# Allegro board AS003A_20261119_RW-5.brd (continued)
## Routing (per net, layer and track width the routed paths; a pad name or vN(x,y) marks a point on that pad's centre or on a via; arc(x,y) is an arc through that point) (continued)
D11813: length 195.8
  L09_DIG w0.081: D118.13 189.31,77.39 189.31,101.16 218.35,130.2 255.78,130.2 272.55,146.97 272.55,151.71 285.02,164.19 285.02,166.46 293.11,174.55 293.11,176.52 294.92,178.34 294.92,190.15 293.55,191.52 293.55,197.45 292.91,198.09 292.91,199.91 292.43,200.39 292.43,201.55
  L09_DIG w0.102: v1(292.83,204.63) 292.43,204.23 292.43,201.55
D11814: length 314.6
  L05_DIG w0.079: D118.14 194.68,80.38 194.68,81.41 196.02,82.75 202.22,82.75 205.57,79.39 205.57,30.02 210.6,24.99 225.11,24.99 226.83,26.71 226.83,126.96 237.73,137.87 237.73,148.71 246.7,157.67 246.7,197.45 252.08,202.84 252.08,208.84 254.24,210.99 260.49,210.99 263.71,214.2 275.91,214.2 276.93,215.22 277.52,215.22 277.73,215.43 277.75,215.43
  L05_DIG w0.102: 277.75,215.43 281.23,215.43 v1(281.63,215.03)
D11815: length 196
  L09_DIG w0.081: 293.23,201.55 293.23,199 294.08,198.15 294.85,198.15 295.38,197.62 295.38,192.76 297.87,190.27 297.87,177.64 286.78,166.56 286.78,162.78 276.08,152.08 276.08,148.13 256.31,128.36 219.19,128.36 194.44,103.61 194.44,77.34 D118.15
  L09_DIG w0.102: 293.23,201.55 293.23,204.23 v1(293.63,204.63)
D11816: length 314.6
  L05_DIG w0.079: D118.16 196.93,79.93 195.48,79.93 195.06,80.35 195.06,81.25 196.18,82.37 202.06,82.37 205.19,79.23 205.19,29.86 210.44,24.61 225.27,24.61 227.21,26.55 227.21,126.8 238.12,137.71 238.12,148.55 247.08,157.51 247.08,197.29 252.47,202.68 252.47,208.68 254.4,210.6 260.65,210.6 263.87,213.82 276.07,213.82 277.09,214.84 277.52,214.84 277.73,214.63 277.75,214.63
  L05_DIG w0.102: v1(280.83,215.03) 280.43,214.63 277.75,214.63
D11901: length 229.7
  L32_DIG w0.081: D119.01 161.29,57.15 161.29,134.87 219.52,193.1 236.15,193.1 246.19,203.13 274.97,203.13 275.69,203.85 275.69,206.66 277.26,208.23 277.75,208.23
  L32_DIG w0.102: 277.75,208.23 278.83,208.23 v1(279.23,207.83)
D11902: length 272.4
  L30_DIG w0.081: 277.75,212.23 276.07,212.23 275.79,211.95 268.6,211.95 264.71,215.84 252.36,215.84 251.76,216.44 224.77,216.44 224.45,216.11 183.11,216.11 154.1,187.1 154.1,123.82 161.14,116.78 161.14,59.84 D119.02
  L30_DIG w0.102: 277.75,212.23 279.63,212.23 v1(280.03,211.83)
D11903: length 273.7
  L32_DIG w0.081: 277.75,206.63 277.24,206.63 276.45,205.84 276.45,202.69 275.43,201.66 249.59,201.66 238.72,190.79 219.99,190.79 216.8,187.6 216.8,149.01 208.67,140.88 173.49,140.88 173.28,141.09 173.28,141.38 173.49,141.59 183.51,141.59 183.72,141.8 183.72,142.09 183.5,142.31 171.51,142.31 166.29,137.09 166.29,57.07 D119.03
  L32_DIG w0.102: v1(282.43,206.23) 282.03,206.63 277.75,206.63
D11904: length 249.7
  L30_DIG w0.081: 277.75,211.43 276.9,211.43 276.13,210.66 268.7,210.66 265.48,213.88 251.68,213.88 250.25,215.32 226.61,215.32 225.03,213.73 206.96,213.73 185.95,192.73 185.95,168.74 184.38,167.16 184.38,159.16 185.51,158.03 185.51,128.64 166.46,109.59 166.46,59.6 D119.04
  L30_DIG w0.102: 277.75,211.43 279.63,211.43 v1(280.03,211.03)
D11905: length 237.1
  L32_DIG w0.081: D119.05 171.47,57.17 171.47,121.74 179.63,129.91 245.93,129.91 263.79,147.77 263.79,194.61 269.21,200.03 278.72,200.03 279.63,200.94 279.63,201.55
  L32_DIG w0.102: 279.63,201.55 279.63,202.63 v1(280.03,203.03)
D11906: length 242.9
  L30_DIG w0.081: 277.75,210.63 276.89,210.63 276.51,210.25 267.98,210.25 265.56,212.68 225.02,212.68 223.94,211.6 207.32,211.6 187.67,191.95 187.67,123.03 171.58,106.94 171.58,59.56 D119.06
  L30_DIG w0.102: 277.75,210.63 279.63,210.63 v1(280.03,210.23)
D11907: length 229
  L32_DIG w0.081: 282.03,201.55 282.03,200.81 280.88,199.66 280.88,197.2 280.15,196.47 277.08,196.47 275.17,194.56 275.17,190.81 271.49,187.13 271.49,161.36 265.73,155.6 265.73,147.42 245.89,127.58 184.98,127.58 176.59,119.19 176.59,57.21 D119.07
  L32_DIG w0.102: 282.03,201.55 282.03,202.63 v1(282.43,203.03)
D11908: length 239.4
  L30_DIG w0.081: D119.08 176.58,59.64 176.58,105.77 188.59,117.77 188.59,190.9 205.49,207.81 219.31,207.81 220.99,209.5 223.81,209.5 226.11,211.8 264.86,211.8 267.63,209.03 277.75,209.03
  L30_DIG w0.102: v1(280.03,208.63) 279.63,209.03 277.75,209.03
D11909: length 225.6
  L32_DIG w0.081: 283.63,201.55 283.63,200.58 282.52,199.47 282.52,197.2 280.13,194.82 279.57,194.82 278.92,194.17 278.92,193.62 277.56,192.26 276.23,192.26 275.61,191.65 275.61,189.58 273.86,187.83 273.86,173.09 272.48,171.71 272.48,157.63 268,153.15 268,147.52 244.58,124.1 185.88,124.1 181.65,119.87 181.65,57.19 D119.09
  L32_DIG w0.102: v1(284.03,203.03) 283.63,202.63 283.63,201.55
D11910: length 235.7
  L30_DIG w0.081: 277.75,208.23 276.05,208.23 275.75,208.53 266.96,208.53 264.7,210.79 253.65,210.79 247.74,204.88 204.05,204.88 190.8,191.63 190.8,139.75 189.74,138.7 189.74,111.63 181.84,103.72 181.84,59.46 D119.10
  L30_DIG w0.102: v1(280.03,207.83) 279.63,208.23 277.75,208.23
D11911: length 276.9
  L32_DIG w0.081: D119.11 186.61,57.07 186.61,113.15 190.58,117.12 218.18,117.12 218.39,116.91 218.39,116.62 218.18,116.41 192.9,116.41 192.7,116.2 192.7,115.91 192.92,115.69 240.09,115.69 270.4,146 270.4,152.07 275.04,156.71 275.04,187.21 277.35,189.53 277.35,190.62 279.58,192.86 283.54,192.86 284.65,193.96 284.65,199.84 285.23,200.43 285.23,201.55
  L32_DIG w0.102: 285.23,201.55 285.23,205.83 v1(285.63,206.23)
D11912: length 232.4
  L30_DIG w0.081: 277.75,207.43 276.8,207.43 275.98,206.61 267.68,206.61 264.41,209.88 254.4,209.88 247.02,202.51 204.37,202.51 192.15,190.28 192.15,108.92 186.76,103.54 186.76,59.62 D119.12
  L30_DIG w0.102: 277.75,207.43 279.63,207.43 v1(280.03,207.03)
D11913: length 212.5
  L32_DIG w0.081: D119.13 191.79,57.17 191.79,104.28 201.16,113.65 241.45,113.65 276.31,148.51 276.31,170.94 277.84,172.47 277.84,188.81 281.15,192.12 284.58,192.12 286.03,193.57 286.03,201.55
  L32_DIG w0.102: v1(286.43,203.03) 286.03,202.63 286.03,201.55
D11914: length 229.4
  L30_DIG w0.081: D119.14 191.56,59.9 191.56,103.3 194.12,105.86 194.12,137.66 193.39,138.38 193.39,189.48 205.22,201.31 225.5,201.31 226.75,200.05 248.47,200.05 255.1,206.68 264.54,206.68 266.2,205.02 275.84,205.02 277.45,206.63 277.75,206.63
  L30_DIG w0.102: v1(280.03,206.23) 279.63,206.63 277.75,206.63
D11915: length 209.9
  L32_DIG w0.081: D119.15 196.87,57.17 196.87,103.79 204.16,111.08 241.23,111.08 277.89,147.74 277.89,170.05 279.19,171.35 279.19,187.9 282.46,191.17 286.23,191.17 288.29,193.23 288.29,200.48 287.63,201.14 287.63,201.55
  L32_DIG w0.102: 287.63,201.55 287.63,202.63 v1(288.03,203.03)
D11916: length 327.7
  L30_DIG w0.081: D119.16 199.32,59.62 199.32,69.33 199.97,69.99 202.65,69.99 205.2,67.44 205.2,13.71 209.18,9.72 226.32,9.72 228.81,12.21 228.81,99.96 233.64,104.79 233.64,183.48 253.35,203.19 275.11,203.19 277.75,205.83
  L30_DIG w0.102: 277.75,205.83 279.63,205.83 v1(280.03,205.43)
D12001: length 313.5
  L07_DIG w0.081: D120.01 152.15,35.56 140.87,46.84 140.87,148.86 151.48,159.47 185.94,159.47 189.83,163.35 189.83,195.87 205.46,211.5 224.25,211.5 224.58,211.83 267.55,211.83 269.25,210.13 275.61,210.13 275.9,209.83 277.75,209.83
  L07_DIG w0.102: v1(282.43,209.43) 282.03,209.83 277.75,209.83
D12002: length 306.8
  L07_DIG w0.081: D120.02 160.53,40.13 152.75,40.13 143.14,49.74 143.14,148.18 153.06,158.1 186.43,158.1 190.87,162.53 190.87,194.51 204.74,208.38 219.79,208.38 220.78,209.37 223.93,209.37 225.38,210.82 267.43,210.82 269.21,209.03 277.75,209.03
  L07_DIG w0.102: v1(281.63,208.63) 281.23,209.03 277.75,209.03
D12003: length 327.9
  L07_DIG w0.081: D120.03 161.55,32.01 148.87,32.01 137.19,43.69 137.19,175.1 174.9,212.82 219.71,212.82 220.65,213.76 224.01,213.76 225.09,212.67 267.97,212.67 269.99,210.65 275.68,210.65 276.46,211.43 277.75,211.43
  L07_DIG w0.102: 277.75,211.43 281.23,211.43 v1(281.63,211.03)
D12004: length 287.9
  L07_DIG w0.081: K5.4 262.35,209.85 252.14,209.85 249.32,207.03 205.01,207.03 192.3,194.32 192.3,161.9 187.03,156.64 154.61,156.64 145.4,147.43 145.4,50.96 154.35,42.02 163.72,42.02 D120.04
D12005: length 369.7
  L34_DIG w0.102: v1(282.43,221.43) 282.03,221.83 277.75,221.83
  L34_DIG w0.104: D120.05 168.96,36.78 168.96,110.56 142.72,136.8 142.72,230.03 154.56,241.88 205.79,241.88 219.95,227.72 225.36,227.72 235.91,238.27 258.98,238.27 267.95,229.3 271.57,229.3 274.11,226.77 274.11,223.34 274.77,222.67 275.89,222.67 276.74,221.83 277.75,221.83
D12006: length 433.8
  L34_DIG w0.102: 277.75,221.03 282.03,221.03 v1(282.43,220.63)
  L34_DIG w0.104: D120.06 171.49,39.33 171.49,111.16 153.01,129.64 153.01,189.61 153.23,189.83 153.53,189.83 153.75,189.61 153.75,132.46 153.98,132.23 154.29,132.23 154.49,132.43 154.49,202.91 174.65,223.06 225.35,223.06 230.63,228.35 271.38,228.35 272.86,226.87 272.86,221.74 273.57,221.03 277.75,221.03
D12007: length 414.8
  L34_DIG w0.102: v1(278.43,219.83) 278.15,219.55 277.75,219.55
  L34_DIG w0.104: 277.75,219.55 273.01,219.55 272.41,220.15 272.41,221.87 267.47,226.81 256.54,226.81 255.64,227.72 233.93,227.72 227.03,220.82 174.23,220.82 173.13,219.72 173.13,218.74 173.53,218.34 219.23,218.34 219.73,217.84 219.73,217.35 219.36,216.99 171.8,216.99 170.82,216.01 170.82,214.29 171.46,213.65 180.89,213.65 181.62,212.92 181.62,211.86 180.89,211.13 173.36,211.13 171.75,209.53 171.75,142.99 167.7,138.94 167.7,117.81 174,111.51 174,36.82 D120.07
D12008: length 279.2
  L34_DIG w0.102: v1(278.43,219.03) 277.75,219.03
  L34_DIG w0.104: 277.75,219.03 271.54,219.03 270.85,219.71 270.85,221.52 266.59,225.78 250.01,225.78 249.22,226.56 234.91,226.56 224.31,215.96 198.09,215.96 172.94,190.81 172.94,141.08 174.51,139.51 174.51,114.35 176.69,112.17 176.69,39.21 D120.08
D12009: length 275.9
  L34_DIG w0.102: 277.75,217.83 282.03,217.83 v1(282.43,217.43)
  L34_DIG w0.104: 277.75,217.83 269.82,217.83 269.1,218.55 269.1,221.04 266.66,223.48 235.16,223.48 225.51,213.83 207.35,213.83 183.66,190.14 183.66,174.33 176.23,166.9 176.23,115.56 179.3,112.5 179.3,36.6 D120.09
D12010: length 270
  L34_DIG w0.102: v1(282.43,216.63) 282.03,217.03 277.75,217.03
  L34_DIG w0.104: 277.75,217.03 275.9,217.03 275.52,217.41 269.38,217.41 268.56,218.23 268.56,220.73 266.5,222.8 235.67,222.8 224.39,211.51 208.23,211.51 185.46,188.74 185.46,174.77 180.38,169.69 180.38,158.31 183.04,155.65 183.04,105.74 181.64,104.35 181.64,39.34 D120.10
D12011: length 263.6
  L34_DIG w0.102: 277.75,215.83 v1(278.43,215.83)
  L34_DIG w0.104: D120.11 184.37,36.61 184.37,103.79 185.9,105.32 185.9,156.8 184.47,158.23 184.47,167.5 186.34,169.37 186.34,187.75 207.07,208.47 220.06,208.47 220.91,209.32 223.7,209.32 235.57,221.18 266.09,221.18 268.03,219.24 268.03,217.78 269.98,215.83 277.75,215.83
D12012: length 256
  L34_DIG w0.102: v1(278.43,214.23) 277.75,214.23
  L34_DIG w0.104: D120.12 186.89,39.17 186.89,104.11 188.39,105.61 188.39,185.71 209.69,207.01 224.83,207.01 237.95,220.14 260.65,220.14 263.25,217.55 267.2,217.55 268.6,216.15 268.6,215.2 269.56,214.23 277.75,214.23
D12013: length 245.8
  L34_DIG w0.102: 277.75,213.43 v1(278.43,213.43)
  L34_DIG w0.104: D120.13 189.15,36.91 189.15,103 190.18,104.02 190.18,169.02 219.12,197.96 224.91,197.96 244.37,217.43 261.55,217.43 262.85,216.13 267.08,216.13 268.01,215.2 268.01,214.02 269.44,212.59 276.91,212.59 277.75,213.43
D12014: length 239.9
  L34_DIG w0.102: v1(278.43,212.63) 277.75,212.63
  L34_DIG w0.104: D120.14 191.81,39.33 191.81,139.74 192.8,140.73 192.8,169.09 219.49,195.78 224.74,195.78 245.39,216.44 260.99,216.44 261.98,215.45 266.92,215.45 267.26,215.12 267.26,214.04 269.36,211.94 277.06,211.94 277.75,212.63
D12015: length 243.4
  L34_DIG w0.102: v1(282.43,211.03) 282.03,211.43 277.75,211.43
  L34_DIG w0.104: D120.15 194.29,36.85 194.29,102.47 195.25,103.42 195.25,169 219.52,193.27 224.61,193.27 247.01,215.67 260.49,215.67 261.85,214.31 266.1,214.31 269.73,210.67 276.25,210.67 277.01,211.43 277.75,211.43
D12016: length 237.4
  L34_DIG w0.102: 277.75,210.63 282.03,210.63 v1(282.43,210.23)
  L34_DIG w0.104: D120.16 196.95,39.27 196.95,168.24 219.99,191.28 223.86,191.28 246.95,214.38 249.29,214.38 250.05,213.61 266.14,213.61 269.63,210.12 276.62,210.12 277.13,210.63 277.75,210.63
D12101: length 133.4
  L07_DIG w0.081: 287.63,201.55 287.63,200.37 286.48,199.22 286.48,197.28 285.37,196.17 284.92,196.17 281.37,192.63 279.45,192.63 277.18,190.36 277.18,189.37 275.1,187.29 275.1,173.18 272.05,170.13 272.05,151.69 272.77,150.97 272.77,144.02 234.8,106.05 234.8,97.64 D121.01
  L07_DIG w0.102: v1(288.03,205.43) 287.63,205.03 287.63,201.55
D12102: length 209.9
  L03_DIG w0.096: 288.83,201.55 288.83,201.53 288.85,201.51 288.85,200.39 289.5,199.73 289.5,193.76 287.5,191.76 284.46,191.76 282.33,189.62 282.33,174.25 279.79,171.71 279.79,161.71 270.08,151.99 270.08,146.47 222.46,98.86 222.46,74.21 224.26,72.42 228.34,72.42 229.88,73.95 229.88,99.58 234.46,104.17 238.61,104.17 239.4,103.38 239.4,101.76 238.17,100.54 237.7,100.54 D121.02
  L03_DIG w0.102: 288.83,201.55 v1(288.83,202.23)
D12103: length 131.6
  L07_DIG w0.081: 288.43,201.55 288.43,199.99 287.75,199.3 287.75,197.11 280.98,190.34 279.64,190.34 277.9,188.6 277.9,174.37 273.23,169.7 273.23,152.35 274.67,150.9 274.67,144.07 239.96,109.35 239.96,97.72 D121.03
  L07_DIG w0.102: 288.43,201.55 288.43,205.03 v1(288.83,205.43)
D12104: length 209.9
  L03_DIG w0.096: 289.23,201.55 289.23,201.53 289.21,201.51 289.21,200.54 289.87,199.88 289.87,193.61 287.65,191.39 284.61,191.39 282.7,189.47 282.7,174.1 280.16,171.56 280.16,161.55 270.44,151.84 270.44,146.32 222.83,98.7 222.83,74.37 224.41,72.79 228.19,72.79 229.51,74.1 229.51,99.74 234.31,104.53 238.76,104.53 239.77,103.53 239.77,100.59 D121.04
  L03_DIG w0.102: 289.23,201.55 289.23,202.63 v1(288.83,203.03)
D12105: length 128.3
  L07_DIG w0.081: D121.05 245.03,97.71 245.03,111.43 276.56,142.96 276.56,150.8 277.85,152.1 277.85,171.37 278.79,172.31 278.79,187.02 284.2,192.43 284.86,192.43 288.22,195.79 288.22,199.17 289.23,200.18 289.23,201.55
  L07_DIG w0.102: v1(289.63,205.43) 289.23,205.03 289.23,201.55
D12106: length 122.7
  L03_DIG w0.096: D121.06 247.81,100.49 248.33,100.49 249.54,101.7 249.54,121.68 282.28,154.42 282.28,172.11 288.78,178.62 288.78,191.12 291.28,193.62 291.28,199.64 292.85,201.2 292.85,201.51 292.83,201.53 292.83,201.55
  L03_DIG w0.102: 292.83,201.55 v1(292.83,202.23)
D12107: length 126.8
  L07_DIG w0.081: 290.03,201.55 290.03,199.89 289.47,199.32 289.47,195.28 285.79,191.6 284.54,191.6 282.54,189.6 282.54,176.78 280.05,174.29 280.05,151.86 278.23,150.04 278.23,142.51 250.11,114.39 250.11,97.71 D121.07
  L07_DIG w0.102: 290.03,201.55 290.03,205.03 v1(290.43,205.43)
D12108: length 122.7
  L03_DIG w0.096: 293.23,201.55 293.23,201.53 293.21,201.51 293.21,201.05 291.65,199.48 291.65,193.47 289.15,190.97 289.15,178.47 282.65,171.96 282.65,154.27 249.91,121.53 249.91,100.61 D121.08
  L03_DIG w0.102: v1(292.83,203.03) 293.23,202.63 293.23,201.55
D12109: length 124.3
  L07_DIG w0.081: 290.83,201.55 290.83,200.01 290.02,199.19 290.02,193.78 285.69,189.46 285.69,177.36 282.16,173.83 282.16,155.27 281.26,154.36 281.26,141.89 255.18,115.81 255.18,97.7 D121.09
  L07_DIG w0.102: v1(291.23,205.43) 290.83,205.03 290.83,201.55
D12110: length 209.5
  L03_DIG w0.096: D121.10 258.34,100.86 258.34,108.82 263.45,113.93 276.44,113.93 280.27,110.1 280.27,77.45 281.83,75.89 288.46,75.89 289.82,77.24 289.82,135.6 287.89,137.53 287.89,155.94 289.25,157.3 289.25,176.49 290.05,177.29 290.05,187.59 294.85,192.39 294.85,199.81 294.05,200.62 294.05,201.51 294.03,201.53 294.03,201.55
  L03_DIG w0.102: 294.03,201.55 294.03,202.63 v1(294.43,203.03)
D12111: length 122.6
  L07_DIG w0.081: 291.63,201.55 291.63,194.2 288.81,191.38 288.81,178.58 284.74,174.52 284.74,155.84 283.58,154.68 283.58,140.02 260.3,116.74 260.3,97.74 D121.11
  L07_DIG w0.102: 291.63,201.55 291.63,205.03 v1(292.03,205.43)
D12112: length 209.5
  L03_DIG w0.096: 294.43,201.55 294.43,201.53 294.41,201.51 294.41,200.77 295.22,199.96 295.22,192.24 290.42,187.44 290.42,177.13 289.62,176.33 289.62,157.15 288.26,155.79 288.26,137.68 290.18,135.76 290.18,77.09 288.61,75.52 281.68,75.52 279.9,77.29 279.9,109.95 276.29,113.56 263.6,113.56 258.71,108.67 258.71,101.11 259.51,100.31 260.37,100.31 D121.12
  L03_DIG w0.102: 294.43,201.55 v1(294.43,202.23)
D12113: length 123.2
  L07_DIG w0.081: 292.43,201.55 292.43,200.03 293.06,199.4 293.06,193.13 292.09,192.15 292.09,187.3 289.62,184.83 289.62,178.65 291.93,176.34 291.93,157.2 290.47,155.73 290.47,143.94 265.38,118.85 265.38,97.74 D121.13
  L07_DIG w0.102: v1(292.83,205.43) 292.43,205.03 292.43,201.55
D12114: length 188.5
  L03_DIG w0.096: D121.14 268.13,100.49 268.61,100.49 269.88,101.76 269.88,104.11 271.47,105.71 274.41,105.71 277.83,102.28 277.83,75.54 280.2,73.18 290.12,73.18 292.73,75.79 292.73,176.81 294.32,178.39 294.32,188.85 296.59,191.13 296.59,200.69 296.85,200.94 296.85,201.51 296.83,201.53 296.83,201.55
  L03_DIG w0.102: 296.83,201.55 v1(296.83,202.23)
D12115: length 121.4
  L07_DIG w0.081: D121.15 270.48,97.76 270.48,120.93 292.96,143.42 292.96,176.67 290.43,179.2 290.43,183.58 293.13,186.29 293.13,191.62 293.62,192.1 293.62,200.05 293.23,200.44 293.23,201.55
  L07_DIG w0.102: v1(293.63,205.43) 293.23,205.03 293.23,201.55
D12116: length 188.5
  L03_DIG w0.096: D121.16 270.25,100.59 270.25,103.96 271.63,105.34 274.25,105.34 277.46,102.13 277.46,75.39 280.05,72.81 290.28,72.81 293.1,75.64 293.1,176.65 294.69,178.24 294.69,188.7 296.96,190.98 296.96,200.54 297.21,200.79 297.21,201.51 297.23,201.53 297.23,201.55
  L03_DIG w0.102: v1(296.83,203.03) 297.23,202.63 297.23,201.55
D12201: length 161
  L09_DIG w0.081: D122.01 231.71,78.17 231.71,102.16 277.9,148.35 277.9,151.65 297.75,171.51 297.75,174.22 301.04,177.51 301.04,188.52 296.65,192.92 296.65,197.4 295.03,199.02 295.03,199.45 294.03,200.45 294.03,201.55
  L09_DIG w0.102: 294.03,201.55 294.03,204.23 v1(294.43,204.63)
D12202: length 314.6
  L05_DIG w0.079: 277.75,213.83 277.73,213.83 277.52,213.62 277.14,213.62 275.93,212.42 268.99,212.42 266.12,209.54 266.12,204.99 264.6,203.48 262.95,203.48 261.46,201.99 261.46,157 256.33,151.87 256.33,131.35 255.05,130.07 253.6,130.07 252.65,131.02 252.65,153.78 258.61,159.75 258.61,195.95 257.12,197.45 252.96,197.45 251.85,196.33 251.85,157.03 250.04,155.23 250.04,145.48 229.54,124.97 229.54,84.35 231.53,82.35 237.15,82.35 237.7,81.79 237.7,80.22 D122.02
  L05_DIG w0.102: v1(281.63,213.43) 281.23,213.83 277.75,213.83
D12203: length 163.3
  L09_DIG w0.081: D122.03 237.56,77.4 237.56,101.58 279.07,143.09 279.07,150.32 293.56,164.81 297.19,164.81 301.96,169.58 301.96,188.88 301.3,189.54 301.3,193.11 301.75,193.56 301.75,197.62 301.05,198.32 297.56,198.32 294.83,201.05 294.83,201.55
  L09_DIG w0.102: v1(295.23,204.63) 294.83,204.23 294.83,201.55
D12204: length 314.6
  L05_DIG w0.079: 277.75,213.03 277.73,213.03 277.52,213.24 277.3,213.24 276.09,212.03 269.15,212.03 266.5,209.38 266.5,204.83 264.76,203.09 263.1,203.09 261.84,201.83 261.84,156.84 256.71,151.71 256.71,131.19 255.21,129.69 253.44,129.69 252.26,130.87 252.26,153.94 258.23,159.91 258.23,195.79 256.96,197.06 253.12,197.06 252.23,196.18 252.23,156.87 250.42,155.07 250.42,145.32 229.92,124.82 229.92,84.51 231.69,82.74 237.3,82.74 238.09,81.95 238.09,80.74 238.71,80.12 239.92,80.12 D122.04
  L05_DIG w0.102: 277.75,213.03 280.43,213.03 v1(280.83,213.43)
D12205: length 190.1
  L09_DIG w0.081: 295.63,201.55 295.63,201.52 297.16,199.98 301.64,199.98 302.33,199.29 302.33,189.88 304.9,187.3 304.9,161.28 298.39,154.77 287.81,154.77 287.61,154.97 287.61,155.27 287.83,155.48 297.26,155.48 297.47,155.69 297.47,155.99 297.26,156.2 287.22,156.2 283.55,152.54 283.55,145.08 242.51,104.04 242.51,77.53 D122.05
  L09_DIG w0.102: v1(296.03,204.63) 295.63,204.23 295.63,201.55
D12206: length 273.7
  L05_DIG w0.079: D122.06 247.61,79.97 248.67,79.97 248.93,80.23 248.93,82.17 249.91,83.15 249.91,107.84 246.95,110.8 242.77,110.8 239.81,107.85 239.81,105.89 237.69,103.77 234.46,103.77 231.76,106.47 231.76,124.34 243.93,136.51 247.87,136.51 249.44,134.94 249.44,130.44 251.6,128.28 256.61,128.28 258.62,130.29 258.62,151.23 261.57,154.18 269.63,154.18 271.64,156.19 271.64,184.74 270.67,185.71 268.33,185.71 267.73,185.11 267.73,158.63 265.99,156.89 264.49,156.89 263.24,158.14 263.24,184.82 266.71,188.29 276.93,188.29 278.07,189.43 278.07,193.01 278.82,193.76 278.82,199.28 280.64,201.1 280.64,201.32 280.43,201.53 280.43,201.55
  L05_DIG w0.102: v1(280.83,204.63) 280.43,204.23 280.43,201.55
D12207: length 193.3
  L09_DIG w0.081: 298.83,201.55 299.77,200.61 302.83,200.61 304.04,199.4 304.04,197.43 304.66,196.81 304.66,190.43 307.5,187.59 307.5,162.27 302.17,156.94 302.17,146.51 271.94,116.28 271.65,116.28 271.44,116.49 271.44,116.79 280.92,126.28 280.92,126.57 280.71,126.78 280.42,126.78 261.35,107.71 253.06,107.71 247.74,102.39 247.74,77.38 D122.07
  L09_DIG w0.102: v1(299.23,204.63) 298.83,204.23 298.83,201.55
D12208: length 273.7
  L05_DIG w0.079: D122.08 249.31,80.89 249.31,82.01 250.3,82.99 250.3,108 247.11,111.19 242.61,111.19 239.43,108.01 239.43,106.05 237.53,104.15 234.62,104.15 232.14,106.63 232.14,124.18 244.09,136.13 247.71,136.13 249.06,134.78 249.06,130.28 251.44,127.89 256.77,127.89 259.01,130.13 259.01,151.07 261.73,153.8 269.79,153.8 272.03,156.03 272.03,184.9 270.83,186.1 268.18,186.1 267.35,185.27 267.35,158.79 265.84,157.28 264.65,157.28 263.63,158.3 263.63,184.66 266.87,187.9 277.09,187.9 278.45,189.27 278.45,192.85 279.2,193.6 279.2,199.12 281.02,200.94 281.02,201.32 281.23,201.53 281.23,201.55
  L05_DIG w0.102: v1(280.83,205.43) 281.23,205.03 281.23,201.55
D12209: length 242.3
  L09_DIG w0.081: 299.63,201.55 299.63,201.51 300,201.15 303.43,201.15 304.95,199.62 304.95,197.76 307.05,195.67 307.05,191.65 308.68,190.03 308.68,156.98 304.57,152.87 304.57,143.8 267.6,106.82 267.33,106.82 267.12,107.03 267.12,107.36 294.46,134.7 294.46,135 294.25,135.21 293.96,135.21 263.31,104.57 255.57,104.57 252.8,101.79 252.8,77.4 D122.09
  L09_DIG w0.102: v1(300.03,204.63) 299.63,204.23 299.63,201.55
D12210: length 327.7
  L05_DIG w0.079: D122.10 258.61,80.81 258.61,81.99 260.11,83.49 260.11,135.04 268.61,143.54 271.71,143.54 277.49,137.76 277.49,103.58 281.99,99.08 281.99,63.06 285.74,59.32 296.03,59.32 298.7,61.99 298.7,93.9 283.31,109.3 283.31,153.28 282.39,154.2 282.39,200.06 283.04,200.71 283.04,201.32 282.83,201.53 282.83,201.55
  L05_DIG w0.102: v1(283.23,205.43) 282.83,205.03 282.83,201.55
D12211: length 242.3
  L09_DIG w0.081: D122.11 260.29,77.41 260.29,89.09 261.48,90.29 279.57,90.29 282.01,87.84 282.01,59.03 283.28,57.76 286.16,57.76 287.31,58.91 287.31,121.05 310.5,144.24 310.5,154.98 312.28,156.76 312.28,176.03 316.83,180.59 316.83,197.69 309.91,204.61 305.6,204.61 304.38,205.83 303.91,205.83
  L09_DIG w0.102: 303.91,205.83 301.23,205.83 v1(300.83,206.23)
D12212: length 327.7
  L05_DIG w0.079: 283.63,201.55 283.63,201.53 283.42,201.32 283.42,200.55 282.77,199.9 282.77,154.36 283.69,153.44 283.69,109.46 299.09,94.06 299.09,61.83 296.18,58.93 285.58,58.93 281.61,62.9 281.61,98.92 277.11,103.42 277.11,137.6 271.56,143.16 268.77,143.16 260.5,134.88 260.5,83.33 258.99,81.83 258.99,80.4 259.61,79.79 260.57,79.79 D122.12
  L05_DIG w0.102: 283.63,201.55 283.63,204.23 v1(283.23,204.63)
D12213: length 224.1
  L09_DIG w0.081: D122.13 265.31,77.35 265.31,78.97 266.59,80.25 275.91,80.25 280.07,76.09 280.07,57.97 283.08,54.97 287.53,54.97 289.82,57.25 289.82,119.9 312.24,142.33 312.24,152.15 315.31,155.21 315.31,169.33 317.95,171.97 317.95,198.42 310.19,206.18 305.87,206.18 304.62,207.43 303.91,207.43
  L09_DIG w0.102: 303.91,207.43 301.23,207.43 v1(300.83,207.83)
D12214: length 212.5
  L05_DIG w0.079: 284.65,201.11 284.65,200.52 285.92,199.24 285.92,192.46 289.07,189.31 289.07,156.88 287.81,155.61 287.81,138.38 290.38,135.81 290.38,106.37 302.47,94.29 302.47,61.89 297.17,56.59 284.69,56.59 279.31,61.98 279.31,78.22 274.77,82.75 269.79,82.75 269.34,82.3 269.34,80.43 269.05,80.15 268.11,80.15 D122.14
  L05_DIG w0.102: 284.65,201.11 284.63,201.14 284.63,201.4 284.43,201.6 284.43,204.23 v1(284.83,204.63)
D12215: length 219.9
  L09_DIG w0.081: D122.15 270.39,75.05 275.5,75.05 278.63,71.92 278.63,56.71 282.36,52.98 289.94,52.98 292.82,55.87 292.82,117.44 317.03,141.64 317.03,153.5 317.67,154.15 317.67,169.74 319,171.07 319,199.81 312.07,206.74 306.26,206.74 304.77,208.23 303.91,208.23
  L09_DIG w0.102: v1(300.83,208.63) 301.23,208.23 303.91,208.23
D12216: length 212.5
  L05_DIG w0.079: 285.03,201.11 285.03,200.68 286.31,199.4 286.31,192.62 289.45,189.47 289.45,156.72 288.19,155.46 288.19,138.54 290.77,135.97 290.77,106.53 302.85,94.45 302.85,61.73 297.33,56.21 284.53,56.21 278.92,61.82 278.92,78.06 274.61,82.37 269.95,82.37 269.72,82.14 269.72,80.8 D122.16
  L05_DIG w0.102: v1(284.83,205.43) 285.23,205.03 285.23,201.6 285.03,201.4 285.03,201.11
D12301: length 181.2
  L32_DIG w0.081: 289.23,201.55 289.23,200.71 289.55,200.39 289.55,193.5 285.94,189.89 282.92,189.89 281.3,188.27 281.3,155.16 279.32,153.18 279.32,145.61 242.75,109.04 237.5,109.04 230.58,102.12 230.58,58.98 D123.01
  L32_DIG w0.102: 289.23,201.55 289.23,205.83 v1(289.63,206.23)
D12302: length 176.7
  L30_DIG w0.081: D123.02 237.6,59.8 237.6,180.69 259.13,202.22 272.35,202.22 272.93,201.64 275.51,201.64 275.87,201.28 279.36,201.28 279.63,201.55
  L30_DIG w0.102: v1(280.03,203.83) 279.63,203.43 279.63,201.55
D12303: length 173.2
  L32_DIG w0.081: 290.03,201.55 290.03,193.25 286.02,189.24 283.6,189.24 282.3,187.95 282.3,154.06 280.89,152.65 280.89,145.32 239.92,104.35 239.92,57.04 D123.03
  L32_DIG w0.102: 290.03,201.55 290.03,205.83 v1(290.43,206.23)
D12304: length 171.9
  L30_DIG w0.081: D123.04 242.86,59.98 242.86,109.25 263.45,129.84 263.45,153.07 261.79,154.73 261.79,197.13 264.64,199.98 275.46,199.98 275.84,200.36 279.9,200.36 280.43,200.89 280.43,201.55
  L30_DIG w0.102: v1(280.83,203.83) 280.43,203.43 280.43,201.55
D12305: length 167.7
  L32_DIG w0.081: D123.05 245.23,57.27 245.23,101.99 285.39,142.15 285.39,153.67 286.68,154.96 286.68,175.83 285.93,176.58 285.93,188.23 291.22,193.52 291.22,199.45 290.83,199.83 290.83,201.55
  L32_DIG w0.102: 290.83,201.55 290.83,202.63 v1(291.23,203.03)
D12306: length 169
  L30_DIG w0.081: 281.23,201.55 281.23,200.22 280.67,199.65 276.59,199.65 276,199.06 268.31,199.06 264.15,194.9 264.15,154.82 265.66,153.31 265.66,140.43 266.67,139.42 266.67,126.66 247.88,107.87 247.88,59.92 D123.06
  L30_DIG w0.102: v1(281.63,203.83) 281.23,203.43 281.23,201.55
D12307: length 168.5
  L32_DIG w0.081: D123.07 250.12,57.08 250.12,104.88 288.29,143.05 288.29,152.97 288.84,153.52 288.84,183.68 291.84,186.68 291.84,199.36 292.43,199.96 292.43,201.55
  L32_DIG w0.102: 292.43,201.55 292.43,205.83 v1(292.03,206.23)
D12308: length 229
  L30_DIG w0.081: D123.08 252.65,59.61 252.65,69.65 255.12,72.13 275.96,72.13 283.69,64.4 283.69,51.08 284.17,50.6 285.73,50.6 286.17,51.04 286.17,100.4 278.92,107.66 278.92,153.5 271.66,160.75 271.66,170.08 274.23,172.64 274.23,185.46 274.62,185.85 274.62,193.1 277.91,196.39 281.91,196.39 282.3,196.78 282.3,199.51 282.03,199.79 282.03,201.55
  L30_DIG w0.102: 282.03,201.55 282.03,203.43 v1(282.43,203.83)
D12309: length 179.1
  L32_DIG w0.081: 293.23,201.55 293.23,186.8 289.77,183.34 289.77,153.65 290.56,152.87 290.56,140.9 257.78,108.12 257.49,108.12 257.28,108.33 257.28,108.64 261.71,113.07 261.71,113.36 261.5,113.57 261.2,113.57 255.35,107.72 255.35,57.23 D123.09
  L32_DIG w0.102: v1(293.63,203.03) 293.23,202.63 293.23,201.55
D12310: length 229
  L30_DIG w0.081: 283.63,201.55 283.63,200.27 282.81,199.44 282.81,194.95 281.32,193.47 277.34,193.47 275.7,191.83 275.7,185.25 275.1,184.64 275.1,171.74 272.55,169.2 272.55,162.77 281.29,154.03 281.29,141.71 282.15,140.85 282.15,106.56 287.54,101.17 287.54,47.79 286.89,47.14 283.18,47.14 282.15,48.18 282.15,62.99 275.18,69.96 258.69,69.96 257.8,69.07 257.8,59.68 D123.10
  L30_DIG w0.102: v1(284.03,203.83) 283.63,203.43 283.63,201.55
D12311: length 188.5
  L32_DIG w0.081: D123.11 260.29,57.09 260.29,107.14 270.39,117.24 270.69,117.24 270.9,117.03 270.9,116.73 262.39,108.23 262.39,107.94 262.61,107.73 262.9,107.73 293.34,138.16 293.34,176.32 294.83,177.81 294.83,201.55
  L32_DIG w0.102: 294.83,201.55 294.83,202.63 v1(295.23,203.03)
D12312: length 225.6
  L30_DIG w0.081: 284.43,201.55 284.43,195.37 283.78,194.71 283.06,194.71 281.26,192.91 279.3,192.91 277.81,191.43 277.81,159.15 283.61,153.35 283.61,107.47 288.98,102.1 288.98,41.24 288.18,40.44 284.59,40.44 284.12,40.91 284.12,41.62 285.3,42.81 285.3,43.41 285.03,43.68 281.15,43.68 280.65,44.19 280.65,62 277.96,64.68 267.88,64.68 D123.12
  L30_DIG w0.102: v1(284.83,203.83) 284.43,203.43 284.43,201.55
D12313: length 190.1
  L32_DIG w0.081: 296.43,201.55 296.43,190.68 297.99,189.12 297.99,178.01 296.59,176.61 296.59,152.41 295.02,150.84 295.02,135.36 267.32,107.66 267.02,107.66 266.81,107.87 266.81,108.17 274.77,116.13 274.77,116.44 274.56,116.65 274.28,116.65 265.5,107.87 265.5,57.22 D123.13
  L32_DIG w0.102: 296.43,201.55 296.43,205.83 v1(296.03,206.23)
D12314: length 225.6
  L30_DIG w0.081: D123.14 270.33,62.05 278.06,62.05 279.09,61.02 279.09,42.34 279.53,41.9 282.69,41.9 283.06,41.53 283.06,40.81 282.66,40.41 280.66,40.41 280.31,40.06 280.31,39.48 280.63,39.16 289.29,39.16 290.59,40.46 290.59,102.93 286.54,106.99 286.54,140.26 285.75,141.05 285.75,154.76 279.74,160.78 279.74,169.95 278.78,170.91 278.78,187.59 280.66,189.46 280.66,190.72 282.94,193.01 285.18,193.01 285.87,193.7 285.87,199.42 285.23,200.06 285.23,201.55
  L30_DIG w0.102: v1(285.63,203.83) 285.23,203.43 285.23,201.55
D12315: length 209.5
  L32_DIG w0.081: 297.23,201.55 297.23,201.06 298.69,199.59 298.69,191.01 301.05,188.65 301.05,178.8 298.01,175.77 298.01,134.32 273.17,109.48 272.9,109.48 272.69,109.69 272.69,110.01 288.62,125.94 288.62,126.24 288.41,126.45 288.11,126.45 270.74,109.08 270.74,57.38 D123.15
  L32_DIG w0.102: 297.23,201.55 297.23,202.63 v1(297.63,203.03)
D12316: length 212.5
  L30_DIG w0.081: 286.03,201.55 286.03,200.13 286.52,199.64 286.52,192.91 285.79,192.18 283.56,192.18 281.53,190.16 281.53,160.8 287.99,154.35 287.99,107.99 292.45,103.53 292.45,40.86 289.67,38.08 280.21,38.08 276.95,41.34 276.95,58.11 275.21,59.85 273.21,59.85 D123.16
  L30_DIG w0.102: v1(286.43,203.83) 286.03,203.43 286.03,201.55
D12401: length 216.3
  L34_DIG w0.102: 277.75,209.43 v1(278.43,209.43)
  L34_DIG w0.104: D124.01 231.98,37.26 231.98,107.35 234.23,109.6 234.23,196.79 250.25,212.81 266.32,212.81 267.66,211.47 267.66,210.38 269.34,208.69 277.01,208.69 277.75,209.43
D12402: length 214.6
  L34_DIG w0.102: v1(282.43,207.83) 282.03,208.23 277.75,208.23
  L34_DIG w0.104: D124.02 234.97,39.35 234.97,105.12 236.13,106.28 236.13,194.43 253.84,212.14 266.25,212.14 267.24,211.14 267.24,209.61 269.76,207.09 276.22,207.09 277.35,208.23 277.75,208.23
D12403: length 213.2
  L34_DIG w0.102: 277.75,207.43 282.03,207.43 v1(282.43,207.03)
  L34_DIG w0.104: 277.75,207.43 277.36,207.43 276.49,206.55 269.35,206.55 265.22,210.68 253.79,210.68 237.53,194.42 237.53,36.79 D124.03
D12404: length 229.4
  L34_DIG w0.102: v1(278.43,206.23) 277.75,206.23
  L34_DIG w0.104: D124.04 239.94,39.46 239.94,133.52 240.15,133.74 240.46,133.74 240.68,133.52 240.68,122.58 240.88,122.37 241.19,122.37 241.41,122.59 241.41,135.06 238.87,137.6 238.87,193.85 254.82,209.8 264.21,209.8 268.58,205.43 276.95,205.43 277.75,206.23
D12405: length 229.4
  L34_DIG w0.102: 277.75,205.43 v1(278.43,205.43)
  L34_DIG w0.104: D124.05 242.55,36.85 242.55,103.09 244.03,104.57 244.03,119.56 243.81,119.78 243.51,119.78 243.29,119.56 243.29,107.17 243.08,106.96 242.77,106.96 242.55,107.18 242.55,140.35 240.97,141.93 240.97,192.01 255.64,206.68 264.35,206.68 266.16,204.87 277.19,204.87 277.75,205.43
D12406: length 229.4
  L34_DIG w0.102: v1(278.43,204.63) 277.75,204.63
  L34_DIG w0.104: 277.75,204.63 276.81,203.69 255.46,203.69 243.32,191.54 243.32,145.3 246.64,141.97 246.64,119.29 246.43,119.07 246.12,119.07 245.9,119.29 245.9,135.13 245.69,135.34 245.38,135.34 245.17,135.13 245.17,39.31 D124.06
D12407: length 193.6
  L34_DIG w0.102: 277.75,203.83 v1(278.43,203.83)
  L34_DIG w0.104: D124.07 247.69,36.79 247.69,144.04 245.69,146.05 245.69,188.82 258.93,202.06 265.85,202.06 267.04,203.25 277.17,203.25 277.75,203.83
D12408: length 187.3
  L34_DIG w0.102: v1(278.43,203.03) 277.75,203.03
  L34_DIG w0.104: 277.75,203.03 276.42,201.7 267.46,201.7 265.39,199.62 261.93,199.62 247.77,185.47 247.77,147.29 251,144.06 251,137.84 250.39,137.22 250.39,39.17 D124.08
D12409: length 184.8
  L34_DIG w0.102: 277.75,201.55 v1(278.43,202.23)
  L34_DIG w0.104: D124.09 252.72,36.84 252.72,144.41 250.06,147.07 250.06,157.47 251.12,158.53 251.12,182.97 267.99,199.84 276.04,199.84 277.75,201.55
D12410: length 184.6
  L34_DIG w0.102: 281.63,201.55 v1(281.63,202.23)
  L34_DIG w0.104: D124.10 255.34,39.3 255.34,136.33 254.59,137.09 254.59,145 252.57,147.01 252.57,183.07 268.64,199.14 276.92,199.14 277.62,199.84 280.97,199.84 281.63,200.49 281.63,201.55
D12411: length 229
  L34_DIG w0.102: v1(282.43,202.23) 282.43,201.55
  L34_DIG w0.104: 282.43,201.55 282.43,198.73 281.8,198.1 279.45,198.1 275.44,194.1 275.44,192.56 256.31,173.42 256.31,147.47 258.34,145.44 260.63,145.44 262.63,143.44 262.63,121.12 262.88,120.88 263.18,120.88 263.37,121.06 263.37,141.81 263.58,142.02 263.89,142.02 264.11,141.81 264.11,110.83 258.06,104.78 258.06,36.58 D124.11
D12412: length 273.7
  L34_DIG w0.102: v1(284.03,206.23) 283.63,205.83 283.63,201.55
  L34_DIG w0.104: D124.12 260.25,39.47 260.25,104.52 266.34,110.61 266.34,145.15 266.56,145.37 266.86,145.37 267.08,145.15 267.08,115.56 267.3,115.34 267.6,115.34 267.82,115.56 267.82,153.7 267.26,154.26 267.26,171.2 267.47,171.42 267.78,171.42 268,171.2 268,156.23 268.24,155.99 268.55,155.99 268.74,156.17 268.74,184.53 276.45,192.25 277.41,192.25 279.11,193.94 279.11,195.6 279.77,196.27 283.41,196.27 284.02,196.87 284.02,199.93 283.63,200.32 283.63,201.55
D12413: length 276.9
  L34_DIG w0.102: 284.43,201.55 284.43,205.83 v1(284.83,206.23)
  L34_DIG w0.104: D124.13 262.92,36.8 262.92,104.22 274.85,116.15 274.85,142.64 274.64,142.85 274.33,142.85 274.11,142.63 274.11,117.96 273.89,117.74 273.59,117.74 273.37,117.96 273.37,143.88 270.34,146.91 270.34,150.07 273.17,152.9 273.17,174.29 272.96,174.5 272.65,174.5 272.43,174.29 272.43,154.81 272.22,154.59 271.91,154.59 271.7,154.81 271.7,183.83 277.35,189.48 277.35,190.32 279.89,192.86 280.76,192.86 282.19,194.29 282.96,194.29 284.43,195.76 284.43,201.55
D12414: length 225.6
  L34_DIG w0.102: 285.63,201.55 v1(285.63,202.23)
  L34_DIG w0.104: D124.14 265.35,39.45 265.35,103.38 276.33,114.37 276.33,166.01 276.62,166.29 276.92,166.29 277.14,166.08 277.14,141.46 277.34,141.25 277.65,141.25 277.88,141.48 277.88,188.74 282.13,192.99 285.17,192.99 285.97,193.79 285.97,199.23 285.63,199.56 285.63,201.55
D12415: length 212.5
  L34_DIG w0.102: v1(286.43,202.23) 286.43,201.55
  L34_DIG w0.104: 286.43,201.55 286.43,192.7 285.83,192.11 283.58,192.11 278.89,187.42 278.89,170.74 279.89,169.75 279.89,152.05 279.02,151.19 279.02,138.15 280.14,137.03 280.14,117.01 279.94,116.81 279.64,116.81 279.4,117.05 279.4,133.78 279.17,134 278.87,134 278.66,133.8 278.66,113.88 268.16,103.38 268.16,36.64 D124.15
D12416: length 177.3
  L34_DIG w0.102: 287.63,201.55 287.63,205.83 v1(288.03,206.23)
  L34_DIG w0.104: D124.16 270.47,39.41 270.47,103.39 281.25,114.16 281.25,188.6 283.73,191.09 286.12,191.09 287.63,192.6 287.63,201.55
D12501: length 344.8
  L09_DIG w0.081: D125.01 13.86,97.68 13.86,102.91 52.98,142.03 63.14,142.03 72.97,151.86 72.97,160.21 149.46,236.7 224.2,236.7 224.89,237.39 250.32,237.39 254.62,233.1 265.63,233.1 269.56,229.16 282.67,229.16 283.63,228.2 283.63,227.71
  L09_DIG w0.102: v1(283.23,224.63) 283.63,225.03 283.63,227.71
D12502: length 378.2
  L03_DIG w0.096: 277.75,226.63 277.61,226.63 277.59,226.61 277.31,226.61 276.87,227.06 276.87,228.24 274.94,230.16 267.4,230.16 245.25,252.31 142.67,252.31 89.75,199.39 89.75,146.86 68.71,125.82 27.62,125.82 16.61,114.81 16.61,100.43 D125.02
  L03_DIG w0.102: v1(279.23,226.23) 278.83,226.63 277.75,226.63
D12503: length 515.3
  L34_DIG w0.102: v1(279.23,227.03) 279.23,227.71
  L34_DIG w0.104: D125.03 18.91,97.65 18.91,200.41 66.33,247.83 126.84,247.83 127.68,248.68 127.68,249.96 126.9,250.73 76.55,250.73 75.81,251.48 75.81,252.45 76.75,253.39 274.45,253.39 276.73,251.12 276.73,242.57 279.23,240.06 279.23,227.71
D12504: length 378.2
  L03_DIG w0.096: 277.75,226.23 277.61,226.23 277.59,226.25 277.16,226.25 276.5,226.9 276.5,228.08 274.79,229.79 267.25,229.79 245.1,251.94 142.82,251.94 90.12,199.24 90.12,146.71 68.86,125.45 27.77,125.45 16.98,114.66 16.98,101.13 18.02,100.09 19.29,100.09 D125.04
  L03_DIG w0.102: 277.75,226.23 v1(278.43,226.23)
D12505: length 515.2
  L34_DIG w0.102: 278.43,227.71 v1(278.43,227.03)
  L34_DIG w0.104: D125.05 24.12,97.78 24.12,119.96 30.49,126.32 96.33,126.32 97.83,127.82 97.83,129.71 96.23,131.32 28.93,131.32 27.58,132.67 27.58,135.5 28.8,136.72 68.62,136.72 132.29,200.39 132.29,232.58 151.15,251.44 271.59,251.44 274.89,248.15 274.89,242.16 278.43,238.61 278.43,227.71
D12506: length 473.7
  L03_DIG w0.096: 277.75,224.63 277.67,224.63 277.59,224.63 277.57,224.61 277.3,224.6 276.28,224.6 276.01,224.88 273.3,224.88 272.77,225.42 272.77,227.81 271.83,228.74 266.09,228.74 262.31,232.52 260.71,232.52 245.03,248.19 143.51,248.19 91.61,196.29 91.61,145.88 68.37,122.65 27.79,122.65 26.77,121.62 26.77,120.25 27.64,119.38 61.11,119.38 61.56,118.94 61.56,117.02 60.9,116.37 21.23,116.37 19.44,114.57 19.44,113.1 21.14,111.4 31.9,111.4 33.04,110.26 33.04,108.71 32.06,107.73 20.94,107.73 19.9,106.69 19.9,105.16 20.61,104.44 26.05,104.44 27.75,102.74 27.75,100.77 27.27,100.3 26.64,100.3 D125.06
  L03_DIG w0.102: 277.75,224.63 v1(278.43,224.63)
D12507: length 394.1
  L34_DIG w0.102: v1(278.43,223.83) 277.75,223.83
  L34_DIG w0.104: D125.07 28.99,97.57 28.99,105.71 42.23,118.96 117.13,118.96 135.58,137.41 135.58,232.04 152.44,248.89 269.04,248.89 273.13,244.8 273.13,242.21 276.49,238.86 276.49,224.58 277.24,223.83 277.75,223.83
D12508: length 473.7
  L03_DIG w0.096: D125.08 28.11,101.43 28.11,102.9 26.2,104.81 20.77,104.81 20.27,105.31 20.27,106.53 21.1,107.36 32.21,107.36 33.41,108.56 33.41,110.41 32.05,111.77 21.29,111.77 19.8,113.25 19.8,114.42 21.39,116 61.05,116 61.92,116.87 61.92,119.09 61.26,119.75 27.79,119.75 27.14,120.4 27.14,121.47 27.95,122.28 68.53,122.28 91.97,145.73 91.97,196.14 143.66,247.83 244.88,247.83 260.55,232.15 262.16,232.15 265.93,228.37 271.68,228.37 272.4,227.65 272.4,225.27 273.15,224.51 275.85,224.51 276.13,224.24 277.31,224.24 277.58,224.24 277.6,224.23 277.68,224.23 277.75,224.23
  L03_DIG w0.102: 277.75,224.23 278.83,224.23 v1(279.23,224.63)
D12509: length 473.7
  L34_DIG w0.102: v1(278.43,223.03) 277.75,223.03
  L34_DIG w0.104: 277.75,223.03 276.54,223.03 275.87,223.7 275.87,237.54 266.13,247.28 154.85,247.28 138.79,231.23 138.79,119.95 132.76,113.92 91.38,113.92 91.15,114.15 91.15,114.46 91.35,114.66 129.45,114.66 129.66,114.87 129.66,115.18 129.45,115.4 45.17,115.4 34.27,104.5 34.27,97.77 D125.09
D12510: length 394.1
  L03_DIG w0.096: D125.10 37.25,100.75 37.25,106.2 44.45,113.4 61.25,113.4 94.09,146.24 94.09,196.89 134.53,237.32 146.21,237.32 146.58,237.69 146.58,238.16 146.17,238.56 143.78,238.56 143.15,239.18 143.15,240.62 143.81,241.28 162.19,241.28 162.61,241.7 162.61,242.44 161.78,243.27 145.58,243.27 144.72,244.13 144.72,245.26 145.9,246.43 241.92,246.43 259.71,228.64 262.8,228.64 265.51,225.92 266.82,225.92 268.23,224.52 268.23,224.12 269.11,223.24 269.61,223.24 270.49,222.36 270.49,221.81 270.97,221.32 275.75,221.32 277.04,222.61 277.59,222.61 277.61,222.63 277.75,222.63
  L03_DIG w0.102: v1(279.23,222.23) 278.83,222.63 277.75,222.63
D12511: length 325.6
  L07_DIG w0.081: 283.63,227.71 283.63,228.77 282.49,229.92 269.48,229.92 268.37,231.02 263.93,231.02 262.43,232.52 250.72,232.52 244.34,238.9 160.29,238.9 39.27,117.88 39.27,97.69 D125.11
  L07_DIG w0.102: 283.63,227.71 283.63,224.23 v1(283.23,223.83)
D12512: length 394.1
  L03_DIG w0.096: 277.75,222.23 277.61,222.23 277.59,222.25 277.19,222.25 275.9,220.95 270.82,220.95 270.12,221.66 270.12,222.21 269.46,222.87 268.95,222.87 267.86,223.96 267.86,224.37 266.67,225.56 265.36,225.56 262.64,228.27 259.56,228.27 241.76,246.06 146.05,246.06 145.09,245.11 145.09,244.28 145.74,243.64 161.94,243.64 162.98,242.59 162.98,241.55 162.34,240.91 143.97,240.91 143.52,240.47 143.52,239.34 143.93,238.93 146.33,238.93 146.95,238.31 146.95,237.53 146.36,236.95 134.68,236.95 94.46,196.74 94.46,146.09 61.41,113.03 44.6,113.03 37.62,106.04 37.62,100.34 37.73,100.23 39.47,100.23 D125.12
  L03_DIG w0.102: 277.75,222.23 v1(278.43,222.23)
D12513: length 378.6
  L07_DIG w0.081: D125.13 44.49,97.83 44.49,117.36 70.69,143.56 70.69,143.86 70.48,144.07 70.19,144.07 49.3,123.18 49.07,123.18 48.86,123.39 48.86,123.76 161.87,236.77 244.58,236.77 250.79,230.56 260.64,230.56 261.32,229.88 267.77,229.88 268.67,228.98 282.06,228.98 282.83,228.2 282.83,227.71
  L07_DIG w0.102: v1(282.43,223.83) 282.83,224.23 282.83,227.71
D12514: length 369.7
  L03_DIG w0.096: D125.14 46.84,100.18 47.2,100.18 48.26,101.24 48.26,106.22 51.27,109.23 59.83,109.23 96.54,145.94 96.54,195.29 137.26,236.01 179.56,236.01 180.12,236.57 180.12,237.43 179.39,238.17 166.5,238.17 165.08,239.58 165.08,242.28 166.82,244.02 242.34,244.02 247.15,239.21 247.15,236.11 257.66,225.59 261.34,225.59 263.69,223.24 267.2,223.24 268.47,221.97 268.47,221.06 270,219.53 275.75,219.53 276.82,220.6 277.3,220.6 277.57,220.61 277.59,220.63 277.67,220.63 277.75,220.63
  L03_DIG w0.102: 277.75,220.63 v1(278.43,220.63)
D12515: length 369.7
  L07_DIG w0.081: D125.15 59.08,85.7 59.08,72.56 61.44,70.2 74.57,70.2 76.16,71.79 76.16,148.77 161.69,234.29 242.88,234.29 247.25,229.93 249.87,229.93 251.54,228.26 267.32,228.26 269.16,226.42 271.72,226.42 273.53,224.61 275.79,224.61 276.98,223.43 277.75,223.43
  L07_DIG w0.102: v1(281.63,223.03) 281.23,223.43 277.75,223.43
D12516: length 369.7
  L03_DIG w0.096: D125.16 48.63,101.23 48.63,106.07 51.42,108.86 59.98,108.86 96.91,145.79 96.91,195.13 137.41,235.64 179.71,235.64 180.49,236.42 180.49,237.58 179.54,238.53 166.65,238.53 165.45,239.74 165.45,242.13 166.97,243.65 242.18,243.65 246.78,239.06 246.78,235.95 257.51,225.22 261.18,225.22 263.54,222.87 267.05,222.87 268.1,221.82 268.1,220.91 269.85,219.16 275.9,219.16 276.97,220.24 277.31,220.24 277.58,220.24 277.6,220.23 277.68,220.23 277.75,220.23
  L03_DIG w0.102: 277.75,220.23 278.83,220.23 v1(279.23,220.63)
D12601: length 414.8
  L30_DIG w0.081: 277.75,221.03 275.16,221.03 274.28,221.91 274.28,223.74 272.4,225.62 272.4,227.52 270.52,229.4 261.61,229.4 260.74,230.27 254.1,230.27 253.02,229.19 237.94,229.19 228.12,239.01 161.88,239.01 84.08,161.22 84.08,137.75 76.53,130.19 30.35,130.19 30.14,130.4 30.14,130.7 30.35,130.91 45.56,130.91 45.77,131.11 45.77,131.41 45.55,131.62 29.24,131.62 14.09,116.47 14.09,77.59 D126.01
  L30_DIG w0.102: 277.75,221.03 279.63,221.03 v1(280.03,220.63)
D12602: length 378.6
  L03_DIG w0.096: D126.02 16.8,80.3 16.8,84.6 23.05,90.84 52.95,90.84 71.18,109.07 71.18,118.56 100,147.39 100,194.84 113.28,208.12 130.44,208.12 135.39,213.08 135.39,217.47 130.99,221.88 130.99,224.51 133.15,226.67 205.5,226.67 208.96,223.21 257.06,223.21 257.48,223.63 260.9,223.63 263.76,220.76 267.03,220.76 270.04,217.75 275.62,217.75 276.48,218.61 277.59,218.61 277.61,218.63 277.75,218.63
  L03_DIG w0.102: v1(279.23,218.23) 278.83,218.63 277.75,218.63
D12603: length 378.6
  L09_DIG w0.081: D126.03 18.96,77.38 18.96,104.97 51.15,137.16 69.18,137.16 76.61,144.59 76.61,156.9 150.33,230.63 167.25,230.63 167.44,230.82 167.44,231.12 167.21,231.34 155.71,231.34 155.5,231.55 155.5,231.85 155.71,232.06 249.66,232.06 251.4,230.32 261.36,230.32 261.9,229.78 266.2,229.78 269.6,226.37 271.79,226.37 273.52,224.63 275.67,224.63 276.07,224.23 277.75,224.23
  L09_DIG w0.102: 277.75,224.23 280.43,224.23 v1(280.83,223.83)
D12604: length 378.6
  L03_DIG w0.096: 277.75,218.23 277.61,218.23 277.59,218.25 276.63,218.25 275.77,217.38 269.89,217.38 266.88,220.39 263.61,220.39 260.74,223.26 257.63,223.26 257.22,222.84 208.81,222.84 205.35,226.3 133.3,226.3 131.35,224.35 131.35,222.03 135.76,217.62 135.76,212.92 130.59,207.75 113.43,207.75 100.37,194.69 100.37,147.23 71.55,118.41 71.55,108.92 53.1,90.47 23.2,90.47 17.17,84.45 17.17,80.34 17.62,79.89 19.17,79.89 D126.04
  L03_DIG w0.102: 277.75,218.23 v1(278.43,218.23)
D12605: length 433.8
  L09_DIG w0.081: 277.75,220.23 276.41,220.23 275.64,220.99 269.08,220.99 267.09,222.99 265.4,222.99 262.48,225.9 254.83,225.9 253.13,227.61 154.83,227.61 154.62,227.4 154.62,227.1 154.83,226.89 196.22,226.89 196.45,226.66 196.45,226.37 196.25,226.18 151,226.18 80.24,155.41 80.24,139.64 72.42,131.82 50.02,131.82 23.81,105.61 23.81,77.15 D126.05
  L09_DIG w0.102: 277.75,220.23 280.43,220.23 v1(280.83,219.83)
D12606: length 378.2
  L03_DIG w0.096: D126.06 26.89,80.23 26.89,87.33 28.6,89.04 54.58,89.04 74.79,109.24 74.79,119.41 126.72,171.34 126.72,173.58 123.23,177.07 119.65,177.07 109.35,166.78 107.22,166.78 105.86,168.14 105.86,170.15 141.21,205.5 160.88,205.5 176.24,220.87 260.69,220.87 263.85,217.71 268.06,217.71 269.78,215.99 275.99,215.99 277.01,217.01 277.71,217.01 277.73,217.03 277.75,217.03
  L03_DIG w0.102: 277.75,217.03 278.83,217.03 v1(279.23,216.63)
D12607: length 342.4
  L09_DIG w0.081: 277.75,217.83 273.36,217.83 272.25,218.94 262.43,218.94 260.36,221.01 251.17,221.01 249.16,223.02 152.87,223.02 84.42,154.58 84.42,137.07 74.67,127.32 51.25,127.32 29.44,105.5 29.44,78.06 27.8,76.43
  L09_DIG w0.102: v1(280.83,217.43) 280.43,217.83 277.75,217.83
D12608: length 378.2
  L03_DIG w0.096: 277.75,216.63 277.73,216.63 277.71,216.65 277.17,216.65 276.14,215.62 269.63,215.62 267.9,217.34 263.69,217.34 260.54,220.5 176.4,220.5 161.03,205.13 141.36,205.13 106.23,170 106.23,168.29 107.37,167.15 109.2,167.15 119.49,177.44 123.38,177.44 127.09,173.73 127.09,171.19 75.16,119.26 75.16,109.09 54.74,88.67 28.75,88.67 27.26,87.18 27.26,80.5 27.86,79.9 29.32,79.9 D126.08
  L03_DIG w0.102: 277.75,216.63 v1(278.43,216.63)
D12609: length 329.9
  L09_DIG w0.081: 33.07,76.12 34.21,77.27 34.21,105.01 52.34,123.15 77.09,123.15 91.57,137.63 91.57,146.1 163.8,218.33 224.61,218.33 225.65,217.29 258.46,217.29 259.98,215.77 269.92,215.77 271.5,214.2 275.65,214.2 276.09,214.63 277.75,214.63
  L09_DIG w0.102: 277.75,214.63 280.43,214.63 v1(280.83,214.23)
D12610: length 314.6
  L03_DIG w0.096: 277.75,211.83 277.73,211.83 277.71,211.81 276.65,211.81 276.07,212.4 270.03,212.4 268.64,213.8 268.64,214.74 267.37,216 263.32,216 262.41,216.91 249.61,216.91 247.86,218.66 176.47,218.66 78.03,120.22 78.03,108.86 56.33,87.16 38.9,87.16 37.39,85.66 37.39,83.23 38.03,82.59 38.03,80.78 37.11,79.86 36.68,79.86 D126.10
  L03_DIG w0.102: 277.75,211.83 v1(278.43,211.83)
D12611: length 322.4
  L09_DIG w0.081: 38.15,76.19 39.27,77.32 39.27,103.94 54.3,118.97 78.09,118.97 95.49,136.37 95.49,145.29 161.93,211.73 224.15,211.73 227.51,215.09 248.93,215.09 251.07,212.95 269.3,212.95 270.02,212.23 277.75,212.23
  L09_DIG w0.102: 277.75,212.23 280.43,212.23 v1(280.83,211.83)
D12612: length 314.6
  L03_DIG w0.096: 277.75,211.43 277.73,211.43 277.71,211.45 276.5,211.45 275.91,212.03 269.88,212.03 268.27,213.65 268.27,214.58 267.22,215.63 263.17,215.63 262.25,216.54 249.45,216.54 247.71,218.29 176.62,218.29 78.4,120.07 78.4,108.7 56.49,86.79 39.05,86.79 37.76,85.5 37.76,83.38 38.4,82.74 38.4,80.98 D126.12
  L03_DIG w0.102: 277.75,211.43 278.83,211.43 v1(279.23,211.83)
D12613: length 314.1
  L09_DIG w0.081: D126.13 44.38,77.4 44.38,103.36 55.77,114.75 79.43,114.75 100.48,135.81 100.48,145.09 162.43,207.03 224.17,207.03 227.77,210.63 277.75,210.63
  L09_DIG w0.102: 277.75,210.63 280.43,210.63 v1(280.83,210.23)
D12614: length 314.6
  L03_DIG w0.096: 277.75,210.63 277.61,210.63 277.59,210.61 270.05,210.61 266.83,213.84 250.76,213.84 248.25,216.35 177.04,216.35 82.36,121.66 82.36,110.37 71.48,99.49 71.48,83.46 67.43,79.41 58.08,79.41 52.44,85.04 50.47,85.04 47.28,81.86 47.28,80.3 D126.14
  L03_DIG w0.102: 277.75,210.63 278.83,210.63 v1(279.23,210.23)
D12615: length 308.3
  L09_DIG w0.081: 277.75,209.03 276.93,209.03 276.34,208.44 269.4,208.44 264.46,203.51 241.5,203.51 240.18,202.18 162.8,202.18 105.53,144.91 105.53,136.04 79.1,109.61 55.45,109.61 49.55,103.71 49.55,77.49 D126.15
  L09_DIG w0.102: 277.75,209.03 280.43,209.03 v1(280.83,208.63)
D12616: length 314.6
  L03_DIG w0.096: 277.75,210.23 277.61,210.23 277.59,210.25 269.9,210.25 266.68,213.47 250.6,213.47 248.1,215.98 177.2,215.98 82.73,121.51 82.73,110.22 71.85,99.34 71.85,83.3 67.58,79.04 57.92,79.04 52.29,84.67 50.62,84.67 47.65,81.7 47.65,80.33 47.9,80.08 49.46,80.08 D126.16
  L03_DIG w0.102: 277.75,210.23 v1(278.43,210.23)
D12701: length 414.8
  L32_DIG w0.081: D127.01 13.93,57.11 13.93,122.27 41.91,150.25 97.48,150.25 109.27,162.05 109.27,217.44 123.79,231.96 225.4,231.96 228.57,228.79 252.23,228.79 257.56,223.45 266.9,223.45 268.93,221.42 275.66,221.42 276.07,221.83 277.75,221.83
  L32_DIG w0.102: 277.75,221.83 278.83,221.83 v1(279.23,221.43)
D12702: length 378.6
  L09_DIG w0.081: D127.02 16.41,59.59 16.41,104.02 51.93,139.54 66.83,139.54 74.23,146.94 74.23,157.6 150.86,234.22 249.76,234.22 251.79,232.2 265.22,232.2 269.15,228.26 282.28,228.26 282.83,227.71
  L09_DIG w0.102: v1(282.43,224.63) 282.83,225.03 282.83,227.71 282.83,227.71
D12703: length 393.9
  L30_DIG w0.081: D127.03 19.06,57.16 19.06,116.25 30,127.19 81.75,127.19 88.71,134.16 88.71,160.58 162.38,234.25 226.94,234.25 233.79,227.4 250.37,227.4 251.6,226.17 268.01,226.17 272.94,221.24 272.94,219.49 273.4,219.03 276.06,219.03 276.45,219.43 277.75,219.43
  L30_DIG w0.102: 277.75,219.43 279.63,219.43 v1(280.03,219.03)
D12704: length 369.7
  L09_DIG w0.081: 277.75,223.43 276.37,223.43 275.92,222.97 269.52,222.97 266.37,226.13 264.99,226.13 262.38,228.73 224.91,228.73 223.84,229.81 220.7,229.81 219.92,229.02 150.88,229.02 78.6,156.74 78.6,142.65 70.42,134.48 50.7,134.48 21.53,105.3 21.53,59.63 D127.04
  L09_DIG w0.102: v1(280.83,223.03) 280.43,223.43 277.75,223.43
